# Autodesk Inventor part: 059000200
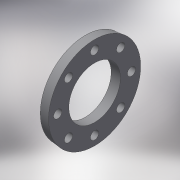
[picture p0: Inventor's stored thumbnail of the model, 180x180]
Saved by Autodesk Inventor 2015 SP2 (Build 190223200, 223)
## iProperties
Created: 2017-10
Part Number: 059000200
Material: Generic
Description: PLASSON BACKING FLANGE PVC 200
Document SubType Name: Modeling
Designer: KIM
Density: 1 g/cm^3
Appearance: Default
Author: KIM
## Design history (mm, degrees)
derived "059000.ipt"
feature "Solid1::059000.ipt"
tag "TaggingFeature1"
body "Solid1"
other parameters: "d0" = 32, "d1" = 233, "d3" = 333.2, "d5" = 22, "d6" = 148.5, "d7" = 32, "d8" = 0, "d10" = 360 deg, "E_" = 233, "H_" = 32, "Dp_" = 297, "S_" = 22
